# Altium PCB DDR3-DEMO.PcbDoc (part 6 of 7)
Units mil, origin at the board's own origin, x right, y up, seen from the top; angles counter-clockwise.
Board outline 2827 x 2165.35 mil, 8 copper layers (TOP, GND02, ART03, ART04, PWR05, ART06, GND07, BOTTOM); 111 components, 133 nets, 5542 pads, 873 vias.
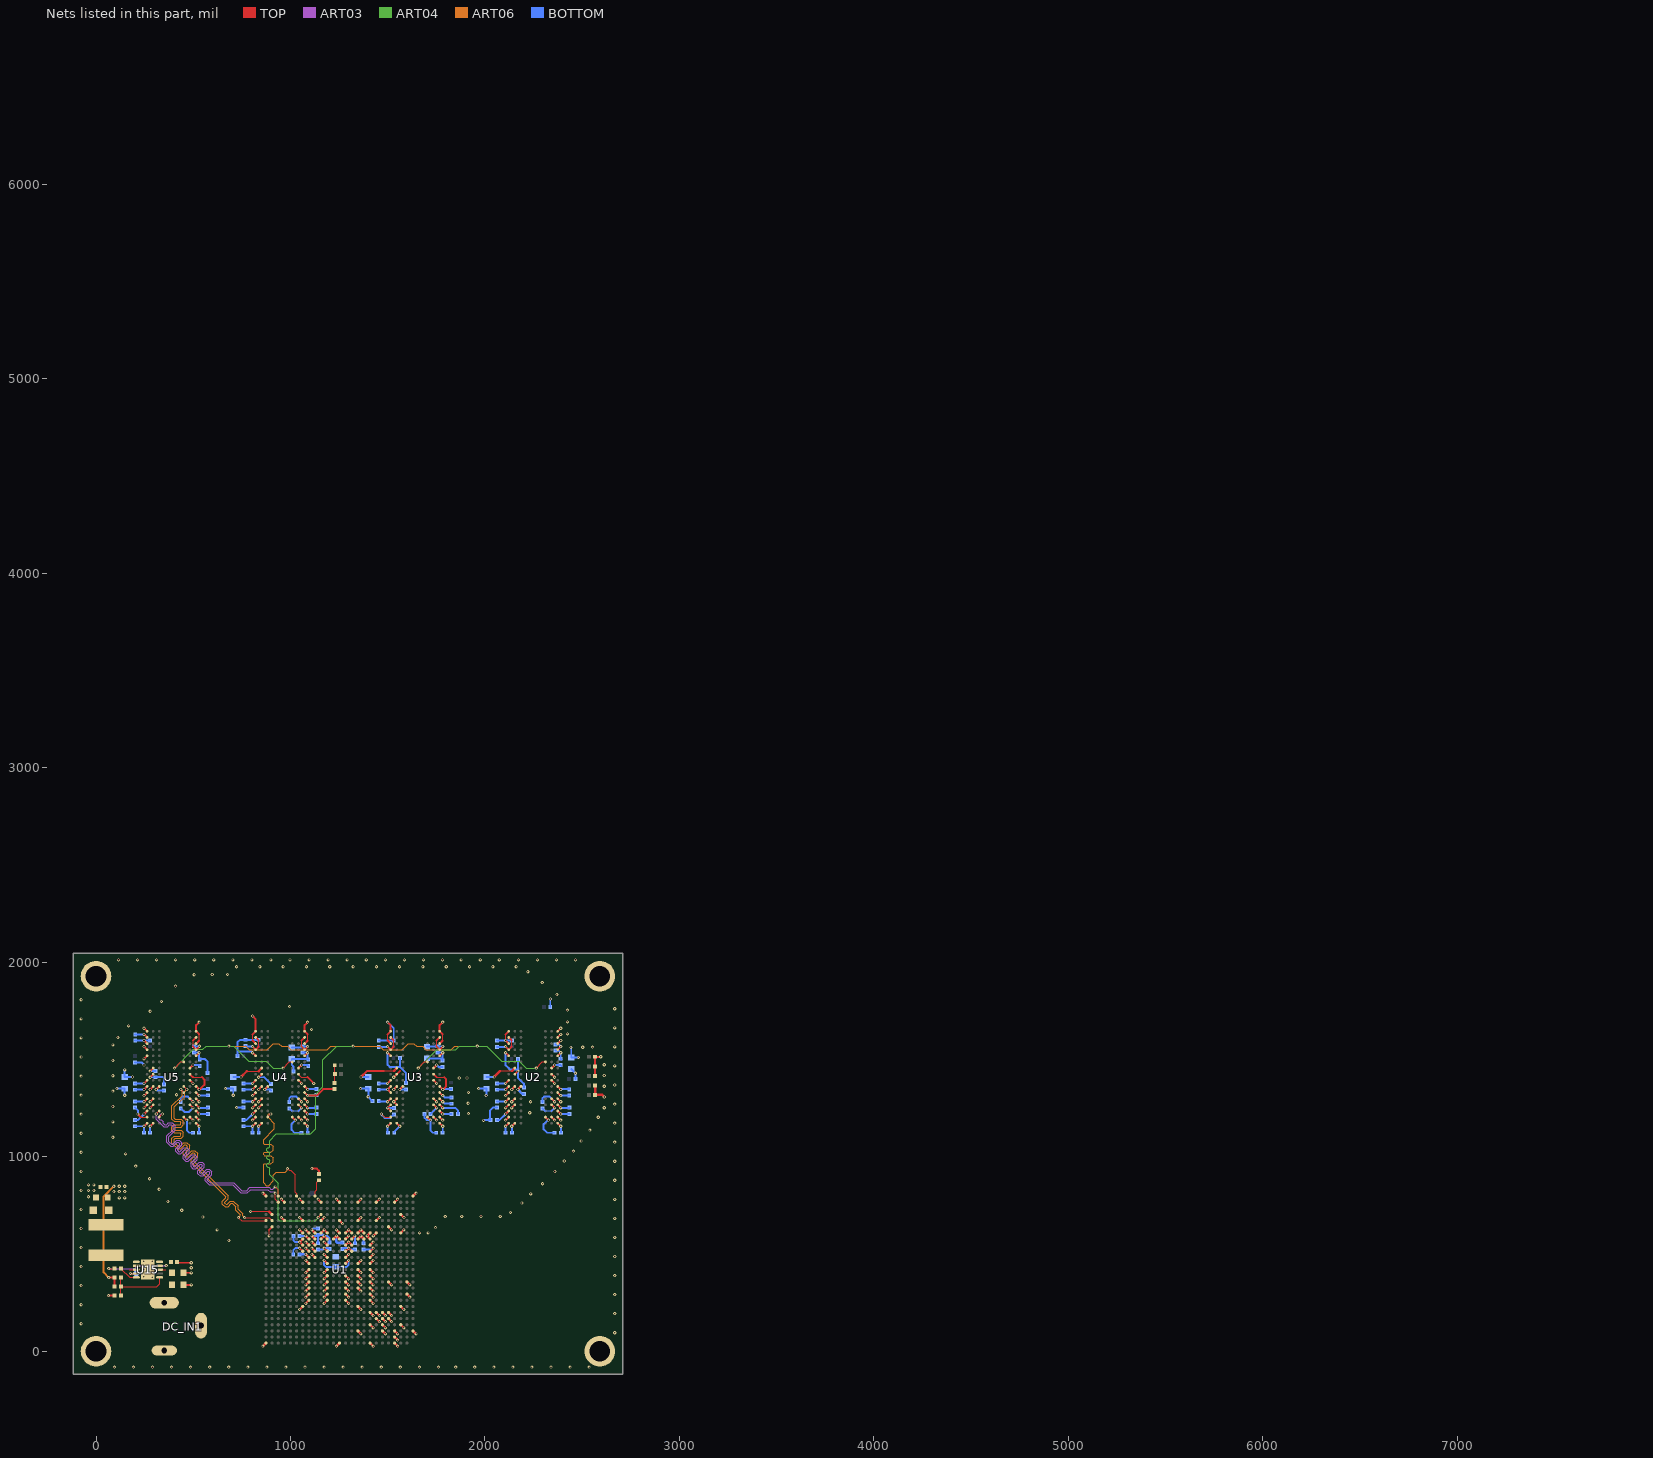
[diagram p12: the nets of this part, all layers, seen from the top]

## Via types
v1: diameter 16, hole 8, TOP to BOTTOM, tented both sides, 873 vias

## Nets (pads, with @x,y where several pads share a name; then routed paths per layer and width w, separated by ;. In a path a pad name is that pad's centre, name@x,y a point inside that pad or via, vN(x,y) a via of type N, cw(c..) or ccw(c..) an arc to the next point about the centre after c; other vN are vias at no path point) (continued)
DRAM_SDQS5_B: U1.AE20 U4.B7 | length 939.2
  TOP w4.5: U4.B7@883.39,1204.41 v1(899.13,1220.15) ; v1(984.19,939.6) 992.94,930.85 999.92,930.85 1023.42,907.35 1023.42,816.9 1031.43,808.89 U1.AE20@1031.43,797.85
  ART06 w5: v1(899.13,1220.15) 888.22,1220.15 882.42,1214.35 882.42,1205.35 917.42,1170.35 917.42,1144.38 861.42,1088.38 861.42,1067.59 865.16,1063.85 899.3,1063.85 910.07,1053.09 910.07,1033.61 899.3,1022.85 865.16,1022.85 861.42,1019.11 861.42,1009.59 865.16,1005.85 899.3,1005.85 910.07,995.09 910.07,975.61 899.3,964.85 865.16,964.85 861.42,961.11 861.42,867.35 876.42,852.35 888.45,852.35 912.42,876.32 912.42,906.35 926.42,920.35 972.42,920.35 984.19,932.12 v1(984.19,939.6)
DRAM_SDQS6: U1.AD23 U5.C7 | length 1353.9
  TOP w4.5: v1(309.66,1220.15) U5.C7@325.41,1235.9 ; v1(921.19,813.6) 921.19,782.11 U1.AD23@936.94,766.36
  ART03 w4.5: v1(309.66,1220.15) 309.66,1193.5 348.23,1154.93 367.84,1154.93 376.77,1163.85 387.07,1163.85 395.92,1155 395.92,1139.7 363.92,1107.7 363.92,1074 383.81,1054.11 397.7,1054.11 418.28,1074.69 423.48,1074.69 429.95,1068.22 429.95,1063.03 409.37,1042.45 409.37,1028.55 421.99,1015.93 435.88,1015.93 456.46,1036.51 461.66,1036.51 468.13,1030.04 468.13,1024.84 447.55,1004.26 447.55,990.37 460.17,977.75 474.07,977.75 497.2,1000.88 502.4,1000.88 508.87,994.41 508.87,989.21 485.74,966.08 485.74,952.18 498.36,939.56 512.25,939.56 535.38,962.69 540.58,962.69 547.05,956.22 547.05,951.03 523.92,927.9 523.92,914 536.54,901.38 550.44,901.38 573.57,924.51 578.76,924.51 585.23,918.04 585.23,912.84 562.1,889.71 562.1,875.82 581.63,856.29 703.63,856.29 744.57,815.35 778.42,815.35 794.92,831.85 883.92,831.85 895.42,820.35 914.44,820.35 v1(921.19,813.6)
DRAM_SDQS6_B: U1.AE23 U5.B7 | length 1356.1
  TOP w4.5: U5.B7@325.41,1204.41 v1(341.15,1220.15) ; v1(921.19,845.09) 936.94,829.34 U1.AE23@936.94,797.85
  ART03 w4.5: v1(341.15,1220.15) 334.22,1220.15 320.16,1206.09 320.16,1197.84 326.66,1191.35 334.42,1191.35 345.54,1180.23 345.54,1172.47 352.58,1165.43 363.5,1165.43 372.42,1174.35 391.42,1174.35 406.42,1159.35 406.42,1135.35 374.42,1103.35 374.42,1078.35 388.15,1064.61 393.35,1064.61 413.93,1085.19 427.83,1085.19 440.45,1072.57 440.45,1058.68 419.87,1038.1 419.87,1032.9 426.34,1026.43 431.54,1026.43 452.11,1047.01 466.01,1047.01 478.63,1034.39 478.63,1020.49 458.05,999.91 458.05,994.72 464.52,988.25 469.72,988.25 492.85,1011.38 506.74,1011.38 519.37,998.76 519.37,984.86 496.24,961.73 496.24,956.53 502.71,950.06 507.9,950.06 531.03,973.19 544.93,973.19 557.55,960.57 557.55,946.68 534.42,923.55 534.42,918.35 540.89,911.88 546.09,911.88 569.22,935.01 583.11,935.01 595.73,922.39 595.73,908.49 572.6,885.36 572.6,880.17 585.98,866.79 707.98,866.79 748.92,825.85 774.07,825.85 790.57,842.35 889.42,842.35 899.42,832.35 908.46,832.35 v1(921.19,845.09) v1@920.93,845.35
DRAM_SDQS7: U1.AA25 U5.F3 | length 1354.2
  TOP w4.5: v1(435.64,1346.14) U5.F3@451.39,1330.39 ; v1(732.22,687.62) 747.97,671.87 U1.AA25@873.95,671.87
  ART06 w5: v1(435.64,1346.14) 443.42,1338.36 443.42,1314.32 390.42,1261.32 390.42,1192.61 401.18,1181.85 432.68,1181.85 436.42,1178.11 436.42,1168.59 432.68,1164.85 401.18,1164.85 390.42,1154.09 390.42,1134.61 401.18,1123.85 432.68,1123.85 436.42,1120.11 436.42,1110.59 432.68,1106.85 401.18,1106.85 390.42,1096.09 390.42,1070.64 420.89,1040.17 436.11,1040.17 456.84,1060.9 462.12,1060.9 468.86,1054.16 468.86,1048.88 448.14,1028.15 448.13,1012.93 461.9,999.16 477.13,999.16 497.85,1019.89 503.14,1019.89 509.87,1013.15 509.87,1007.87 489.15,987.14 489.15,971.92 666.76,794.3 666.76,789.02 650.15,772.4 650.15,757.18 663.92,743.41 679.14,743.41 695.76,760.02 701.04,760.02 718.42,742.64 718.42,726.22 741.97,702.67 741.97,697.36 v1(732.22,687.62)
DRAM_SDQS7_B: U1.AA24 U5.G3 | length 1355.8
  TOP w4.5: U5.G3@451.39,1361.89 v1(467.14,1346.14) ; v1(763.71,687.62) 889.69,687.62 U1.AA24@905.44,671.87
  ART06 w5: v1(467.14,1346.14) 455.42,1334.42 455.42,1309.35 402.42,1256.35 402.42,1197.59 406.16,1193.85 437.66,1193.85 448.42,1183.09 448.42,1163.61 437.66,1152.85 406.16,1152.85 402.42,1149.11 402.42,1139.59 406.16,1135.85 437.66,1135.85 448.42,1125.09 448.42,1105.61 437.66,1094.85 406.16,1094.85 402.42,1091.11 402.42,1075.61 425.86,1052.17 431.14,1052.17 451.87,1072.9 467.09,1072.9 480.86,1059.13 480.86,1043.91 460.14,1023.18 460.13,1017.9 466.87,1011.16 472.16,1011.16 492.88,1031.89 508.11,1031.89 521.87,1018.12 521.87,1002.9 501.15,982.17 501.15,976.89 678.76,799.27 678.76,784.05 662.15,767.43 662.15,762.15 668.89,755.41 674.17,755.41 690.79,772.02 706.01,772.02 730.42,747.61 730.42,731.19 753.97,707.64 753.97,697.36 v1(763.71,687.62)
DRAM_WE_B: U1.AB16 U2.L3 U3.L3 U4.L3 U5.L3 | length 4486.2
  TOP w6: v1(404.15,1456.37) 435.65,1487.87 U5.L3@451.39,1487.87 ; v1(962.13,1456.37) 993.63,1487.87 U4.L3@1009.37,1487.87 ; v1(1141.66,687.61) U1.AB16@1157.41,703.36 ; v1(1656.65,1456.37) 1688.15,1487.87 U3.L3@1703.89,1487.87 ; v1(2263.66,1456.37) 2295.16,1487.87 U2.L3@2310.9,1487.87
  ART04 w6: v1(404.15,1456.37) 500.13,1552.35 548.89,1552.35 566.02,1569.48 v1(683.14,1569.48) 707.76,1569.48 785.89,1491.35 875.91,1491.35 910.89,1456.37 v1(962.13,1456.37) ; v1(1141.66,687.61) 1125.92,671.87 942.9,671.87 936.95,677.82 936.95,862.82 892.42,907.35 892.42,941.35 887.42,946.35 881.99,946.35 876.99,951.35 876.99,961.35 881.99,966.35 887.42,966.35 892.42,971.35 892.42,981.35 887.42,986.35 881.99,986.35 876.99,991.35 876.99,1001.35 881.99,1006.35 887.42,1006.35 892.42,1011.35 892.42,1021.35 887.42,1026.35 881.99,1026.35 876.99,1031.35 876.99,1041.35 881.99,1046.35 887.42,1046.35 892.42,1051.35 892.42,1083.35 926.42,1117.35 1103.42,1117.35 1129.42,1143.35 1129.42,1322.35 1166.42,1359.35 1166.42,1498.35 1237.55,1569.48 v1(1321.65,1569.48) ; v1(1656.65,1456.37) 1751.63,1551.35 1849.42,1551.35 1867.55,1569.48 v1(1960.15,1569.48) 2009.29,1569.48 2087.42,1491.35 2177.44,1491.35 2212.42,1456.37 v1(2263.66,1456.37)
  ART06 w4.1: v1(683.14,1569.48) 769.42,1569.48 787.55,1551.35 879.92,1551.35 910.92,1582.35 939.05,1582.35 954.05,1567.35 984.92,1567.35 1000.92,1551.35 1187.78,1551.35 1205.91,1569.48 v1(1321.65,1569.48) 1459.29,1569.48 1477.42,1551.35 1574.42,1551.35 1605.42,1582.35 1633.55,1582.35 1648.55,1567.35 1679.42,1567.35 1695.42,1551.35 1826.29,1551.35 1844.42,1569.48 v1(1960.15,1569.48)
GND: C76.2 C77.2 C78.2 C79.2 C81.2 C82.2 C83.2 C84.2 C85.2 C86.2 C87.2 C88.2 C89.2 C90.2 C91.2 C92.2 C93.2 C94.2 C95.2 C96.2 C97.2 C98.2 C99.2 C100.2 C101.2 C102.2 C103.2 C104.2 C105.2 C106.2 C107.2 C108.2 C109.2 C111.2 C112.2 C113.2 C114.2 C115.2 C116.2 C117.2 C118.2 C119.2 C120.2 C121.2 C122.2 C123.2 C124.2 C125.2 C126.2 C127.2 C128.2 C129.2 C130.2 C131.2 C132.2 C133.2 C134.2 C135.2 C136.2 C137.2 C138.2 C141.2 C142.2 C143.2 C144.2 C145.2 C146.2 C147.2 C148.2 C149.2 C150.2 C151.2 C152.2 C153.2 C154.2 C212.2 C213.2 C214.2 C216.2 C217.2 C218.2 DC_IN1.3 DC_IN1.4 M1.1 M2.1 M3.1 M4.1 R66.1 R67.1 R68.1 R70.2 R71.1 R72.1 R73.2 R135.2 U1.A4 U1.A8 U1.A13 U1.A25 U1.AA7 U1.AA10 U1.AA13 U1.AA16 U1.AA19 U1.AA22 U1.AB3 U1.AB24 U1.AD4 U1.AD7 U1.AD10 U1.AD13 U1.AD16 U1.AD19 U1.AD22 U1.AE1 U1.AE25 U1.B4 U1.C1 U1.C4 U1.C6 U1.C10 U1.D3 U1.D6 U1.D8 U1.E5 U1.E6 U1.E7 U1.F5 U1.F6 U1.F7 U1.F8 U1.G3 U1.G10 U1.G19 U1.H8 U1.H12 U1.H15 U1.H18 U1.J2 U1.J8 U1.J12 U1.J15 U1.J18 U1.K8 U1.K10 U1.K12 U1.K15 U1.K18 U1.L2 U1.L5 U1.L8 U1.L10 U1.L12 U1.L15 U1.L18 U1.M8 U1.M10 U1.M12 U1.M15 U1.M18 U1.N8 U1.N10 U1.N15 U1.N18 U1.P8 U1.P10 U1.P12 U1.P15 U1.P18 U1.R8 U1.R12 U1.R15 U1.R17 U1.T8 U1.T11 U1.T12 U1.T15 U1.T17 U1.T19 U1.U8 U1.U11 U1.U12 U1.U15 U1.U17 U1.U19 U1.V8 U1.V19 U1.W3 U1.W7 U1.W8 U1.W9 U1.W10 U1.W11 U1.W12 U1.W13 U1.W15 U1.W16 U1.W17 U1.W18 U1.W19 U1.Y5 U1.Y24 U2.A9 U2.B1 U2.B3 U2.B9 U2.D1 U2.D8 U2.E1 U2.E2 U2.E8 U2.F9 U2.G1 U2.G8 U2.G9 U2.J2 U2.J8 U2.M1 U2.M9 U2.P1 U2.P9 U2.T1 U2.T9 U3.A9 U3.B1 U3.B3 U3.B9 U3.D1 U3.D8 U3.E1 U3.E2 U3.E8 U3.F9 U3.G1 U3.G8 U3.G9 U3.J2 U3.J8 U3.M1 U3.M9 U3.P1 U3.P9 U3.T1 U3.T9 U4.A9 U4.B1 U4.B3 U4.B9 U4.D1 U4.D8 U4.E1 U4.E2 U4.E8 U4.F9 U4.G1 U4.G8 U4.G9 U4.J2 U4.J8 U4.M1 U4.M9 U4.P1 U4.P9 U4.T1 U4.T9 U5.A9 U5.B1 U5.B3 U5.B9 U5.D1 U5.D8 U5.E1 U5.E2 U5.E8 U5.F9 U5.G1 U5.G8 U5.G9 U5.J2 U5.J8 U5.M1 U5.M9 U5.P1 U5.P9 U5.T1 U5.T9 U15.G1 | length 10545.4
  TOP w6: 230.92,1204.41 U5.B9@262.42,1204.41 ; 498.42,1409.35 545.42,1409.35 ; 530.13,1598.11 530.13,1629.6 ; v1(795.2,719.11) 826.69,719.11 889.69,719.11 ; 804.65,1598.11 804.65,1629.6 ; v1(889.69,593.13) 889.69,624.62 ; U4.J2@1040.87,1424.88 1056.4,1409.35 1087.88,1409.35 ; 1088.11,1598.11 1088.11,1629.6 ; v1(1467.67,1220.15) 1483.41,1204.41 U3.B9@1514.92,1204.41 ; 1499.17,1598.11 1499.17,1629.6 ; 1750.92,1409.35 1790.42,1409.35 ; 1782.63,1598.11 1782.63,1629.6 ; v1(2106.18,1598.11) 2106.18,1629.6
  TOP w10: v1(63.42,286.35) 63.88,285.89 R135.2@95.61,285.89 ; v1(215.18,1220.15) 230.92,1204.41 ; v1(246.67,1157.16) U5.A9@262.42,1172.91 ; v1(246.67,1314.64) U5.F9@262.42,1330.39 ; v1(246.67,1346.14) U5.G9@262.42,1361.89 ; v1(246.67,1503.62) U5.M9@262.42,1519.37 ; v1(246.67,1598.11) U5.P9@262.42,1582.36 ; v1(246.67,1661.1) U5.T9@262.42,1645.35 ; v1(278.16,1251.65) U5.D8@293.91,1267.4 ; v1(278.16,1283.14) U5.E8@293.91,1298.89 ; v1(278.16,1346.14) U5.G8@293.91,1361.89 ; v1(278.16,1409.13) U5.J8@293.91,1424.88 ; C213.2@417.17,459.89 417.17,455.35 v1(489.42,455.35) ; C212.2@449.73,341.89 489.42,341.89 v1(489.42,341.35) ; C214.2@449.73,403.89 v1@489.42,403.89 ; U5.B3@451.39,1204.41 v1(467.14,1188.66) ; U5.E2@482.89,1298.89 v1(498.64,1283.14) ; U5.J2@482.89,1424.88 498.42,1409.35 ; U5.B1@514.38,1204.41 v1(530.13,1188.66) ; U5.D1@514.38,1267.4 v1(530.13,1251.65) ; U5.E1@514.38,1298.89 v1(530.13,1283.14) ; U5.G1@514.38,1361.89 v1(530.13,1346.14) 534.21,1346.14 557.42,1369.35 557.42,1397.35 545.42,1409.35 ; U5.M1@514.38,1519.37 v1(530.13,1535.12) ; U5.P1@514.38,1582.36 530.13,1598.11 ; 530.13,1629.6 U5.T1@514.38,1645.35 514.38,1676.84 v1(530.13,1692.59) ; v1(804.65,1157.16) U4.A9@820.4,1172.91 ; v1(804.65,1188.66) U4.B9@820.4,1204.41 ; v1(804.65,1314.64) U4.F9@820.4,1330.39 ; v1(804.65,1346.14) U4.G9@820.4,1361.89 ; v1(804.65,1535.12) U4.M9@820.4,1519.37 ; 804.65,1598.11 U4.P9@820.4,1582.36 ; 804.65,1629.6 U4.T9@820.4,1645.35 820.4,1708.34 v1(804.65,1724.09) ; v1(836.14,1251.65) U4.D8@851.89,1267.4 ; v1(836.14,1283.14) U4.E8@851.89,1298.89 ; v1(836.14,1346.14) U4.G8@851.89,1361.89 ; v1(836.14,1409.13) U4.J8@851.89,1424.88 ; 889.69,624.62 U1.Y24@905.44,640.37 ; U4.B3@1009.37,1204.41 v1(1025.12,1188.66) ; U4.E2@1040.87,1298.89 v1(1056.62,1283.14) ; U4.B1@1072.36,1204.41 v1(1088.11,1188.66) ; U4.D1@1072.36,1267.4 v1(1088.11,1251.65) ; U4.E1@1072.36,1298.89 v1(1088.11,1283.14) ; U4.G1@1072.36,1361.89 v1(1088.11,1346.14) ; U4.M1@1072.36,1519.37 v1(1088.11,1535.12) ; U4.P1@1072.36,1582.36 1088.11,1598.11 ; 1087.88,1409.35 v1(1119.6,1377.63) ; 1088.11,1629.6 U4.T1@1072.36,1645.35 1072.36,1676.84 v1(1088.11,1692.59) ; v1(1110.17,939.57) 1135.2,939.57 1146.42,928.35 R73.2@1146.42,911.63 ; v1(1499.17,1157.16) U3.A9@1514.92,1172.91 ; v1(1499.17,1535.12) U3.M9@1514.92,1519.37 ; 1499.17,1598.11 U3.P9@1514.92,1582.36 ; 1499.17,1629.6 U3.T9@1514.92,1645.35 1514.92,1676.84 v1(1499.17,1692.59) ; U3.F9@1514.92,1330.39 v1(1499.17,1346.14) U3.G9@1514.92,1361.89 ; v1(1530.66,1346.14) U3.G8@1546.41,1361.89 ; v1(1530.66,1409.13) U3.J8@1546.41,1424.88 1562.16,1440.63 ; U3.D8@1546.41,1267.4 v1(1530.66,1283.14) U3.E8@1546.41,1298.89 ; U3.B3@1703.89,1204.41 v1(1719.64,1188.66) ; U3.E2@1735.39,1298.89 v1(1751.14,1283.14) ; U3.J2@1735.39,1424.88 1750.92,1409.35 ; U3.B1@1766.88,1204.41 v1(1782.63,1188.66) ; U3.D1@1766.88,1267.4 v1(1782.63,1251.65) ; U3.E1@1766.88,1298.89 v1(1782.63,1283.14) ; U3.G1@1766.88,1361.89 v1(1782.63,1346.14) 1784.21,1346.14 1800.42,1362.35 1800.42,1399.35 1790.42,1409.35 ; U3.M1@1766.88,1519.37 v1(1782.63,1535.12) ; U3.P1@1766.88,1582.36 1782.63,1598.11 ; 1782.63,1629.6 U3.T1@1766.88,1645.35 1766.88,1676.84 v1(1782.63,1692.59) ; v1(2106.18,1157.16) U2.A9@2121.93,1172.91 ; v1(2106.18,1188.66) U2.B9@2121.93,1204.41 ; v1(2106.18,1314.64) U2.F9@2121.93,1330.39 ; v1(2106.18,1346.14) U2.G9@2121.93,1361.89 ; v1(2106.18,1535.12) U2.M9@2121.93,1519.37 ; v1(2106.18,1598.11) U2.P9@2121.93,1582.36 ; 2106.18,1629.6 U2.T9@2121.93,1645.35 ; v1(2137.67,1251.65) U2.D8@2153.42,1267.4 ; v1(2137.67,1283.14) U2.E8@2153.42,1298.89 ; v1(2137.67,1346.14) U2.G8@2153.42,1361.89 ; U2.J8@2153.42,1424.88 v1(2169.17,1440.63) ; U2.B3@2310.9,1204.41 v1(2326.65,1188.66) ; U2.E2@2342.4,1298.89 v1(2358.15,1283.14) ; U2.J2@2342.4,1424.88 v1(2358.15,1409.13) ; U2.B1@2373.89,1204.41 v1(2389.64,1188.66) ; U2.D1@2373.89,1267.4 v1(2389.64,1251.65) ; U2.E1@2373.89,1298.89 v1(2389.64,1283.14) ; U2.G1@2373.89,1361.89 v1(2389.64,1346.14) ; U2.M1@2373.89,1519.37 v1(2389.64,1535.12) ; U2.P1@2373.89,1582.36 v1(2389.64,1598.11) ; U2.T1@2373.89,1645.35 v1(2389.64,1661.1) ; R70.2@2566.7,1416.35 C81.2@2566.7,1465.35 C82.2@2566.7,1514.35 v1(2595.42,1514.35)
  TOP w12: v1(858.2,26.2) U1.A25@873.95,41.95 ; v1(858.2,813.6) U1.AE25@873.95,797.85 ; 889.69,719.11 U1.AB24@905.44,703.36 ; v1(952.69,687.62) U1.AA22@968.44,671.87 ; v1(952.69,782.11) U1.AD22@968.44,766.36 ; v1(1047.17,215.17) U1.G19@1062.92,230.92 ; v1(1047.17,530.14) U1.T19@1062.92,514.39 ; v1(1047.17,624.63) U1.W19@1062.92,608.88 ; v1(1047.17,687.62) U1.AA19@1062.92,671.87 ; v1(1047.17,782.11) U1.AD19@1062.92,766.36 ; U1.U19@1062.92,545.88 v1(1047.17,561.63) U1.V19@1062.92,577.38 ; v1(1078.67,246.67) U1.H18@1094.42,262.42 ; v1(1078.67,278.17) U1.J18@1094.42,293.92 ; v1(1078.67,309.66) U1.K18@1094.42,325.41 ; v1(1078.67,341.16) U1.L18@1094.42,356.91 ; v1(1078.67,372.65) U1.M18@1094.42,388.4 ; v1(1078.67,404.15) U1.N18@1094.42,419.9 ; v1(1078.67,467.15) U1.P18@1094.42,451.4 ; v1(1078.67,624.63) U1.W18@1094.42,608.88 ; v1(1110.17,498.64) U1.R17@1125.92,482.89 ; v1(1110.17,530.14) U1.T17@1125.92,514.39 ; v1(1110.17,561.63) U1.U17@1125.92,545.88 ; v1(1110.17,624.63) U1.W17@1125.92,608.88 ; v1(1141.66,782.11) U1.AD16@1157.41,766.36 ; U1.W16@1157.41,608.88 v1(1173.16,624.63) U1.W15@1188.91,608.88 ; U1.AA16@1157.41,671.87 v1(1173.16,687.62) ; v1(1173.16,246.67) U1.H15@1188.91,262.42 ; v1(1173.16,278.17) U1.J15@1188.91,293.92 ; v1(1173.16,309.66) U1.K15@1188.91,325.41 ; v1(1173.16,341.16) U1.L15@1188.91,356.91 ; v1(1173.16,372.65) U1.M15@1188.91,388.4 ; v1(1173.16,404.15) U1.N15@1188.91,419.9 ; v1(1173.16,467.15) U1.P15@1188.91,451.4 ; v1(1173.16,498.64) U1.R15@1188.91,482.89 ; v1(1173.16,530.14) U1.T15@1188.91,514.39 ; v1(1173.16,561.63) U1.U15@1188.91,545.88 ; v1(1236.15,26.2) U1.A13@1251.9,41.95 ; v1(1236.15,624.63) U1.W13@1251.9,608.88 ; v1(1236.15,782.11) U1.AD13@1251.9,766.36 ; U1.AA13@1251.9,671.87 v1(1267.65,656.12) ; U1.H12@1283.4,262.42 v1(1299.15,246.67) ; U1.J12@1283.4,293.92 v1(1299.15,278.17) ; U1.K12@1283.4,325.41 v1(1299.15,309.66) ; U1.L12@1283.4,356.91 v1(1299.15,341.16) ; U1.M12@1283.4,388.4 v1(1299.15,372.65) ; U1.P12@1283.4,451.4 v1(1299.15,467.15) ; U1.R12@1283.4,482.89 v1(1299.15,498.64) ; U1.T12@1283.4,514.39 v1(1299.15,530.14) U1.T11@1314.89,514.39 ; U1.U12@1283.4,545.88 v1(1299.15,561.63) U1.U11@1314.89,545.88 ; U1.W12@1283.4,608.88 v1(1299.15,624.63) U1.W11@1314.89,608.88 ; U1.C10@1346.39,104.94 v1(1362.14,89.19) ; U1.G10@1346.39,230.92 v1(1362.14,215.17) ; U1.K10@1346.39,325.41 v1(1362.14,309.66) ; U1.L10@1346.39,356.91 v1(1362.14,341.16) ; U1.M10@1346.39,388.4 v1(1362.14,372.65) ; U1.N10@1346.39,419.9 v1(1362.14,404.15) ; U1.P10@1346.39,451.4 v1(1362.14,467.15) ; U1.W10@1346.39,608.88 v1(1362.14,624.63) U1.W9@1377.88,608.88 ; U1.AA10@1346.39,671.87 v1(1362.14,687.62) ; U1.AD10@1346.39,766.36 v1(1362.14,782.11) ; U1.A8@1409.38,41.95 v1(1425.13,26.2) ; U1.D8@1409.38,136.44 v1(1425.13,120.69) ; U1.F8@1409.38,199.43 v1(1425.13,183.68) ; U1.H8@1409.38,262.42 v1(1425.13,246.67) ; U1.J8@1409.38,293.92 v1(1425.13,278.17) ; U1.K8@1409.38,325.41 v1(1425.13,309.66) ; U1.L8@1409.38,356.91 v1(1425.13,341.16) ; U1.M8@1409.38,388.4 v1(1425.13,372.65) ; U1.N8@1409.38,419.9 v1(1425.13,404.15) ; U1.P8@1409.38,451.4 v1(1425.13,467.15) ; U1.R8@1409.38,482.89 v1(1425.13,498.64) ; U1.T8@1409.38,514.39 v1(1425.13,530.14) ; U1.U8@1409.38,545.88 v1(1425.13,561.63) ; U1.V8@1409.38,577.38 v1(1393.63,593.13) U1.W8@1409.38,608.88 ; v1(1425.13,593.13) U1.W7@1440.88,608.88 ; U1.E7@1440.88,167.93 v1(1456.63,152.18) ; U1.F7@1440.88,199.43 v1(1456.63,183.68) ; U1.AA7@1440.88,671.87 v1(1456.63,687.62) ; U1.AD7@1440.88,766.36 v1(1456.63,782.11) ; U1.C6@1472.37,104.94 v1(1488.12,89.19) ; U1.D6@1472.37,136.44 v1(1488.12,120.69) ; U1.E6@1472.37,167.93 v1(1488.12,152.18) ; U1.F6@1472.37,199.43 v1(1488.12,183.68) ; U1.E5@1503.87,167.93 v1(1519.62,152.18) ; U1.F5@1503.87,199.43 v1(1519.62,183.68) ; U1.L5@1503.87,356.91 v1(1519.62,341.16) ; U1.Y5@1503.87,640.37 v1(1519.62,624.62) ; U1.A4@1535.36,41.95 v1(1551.11,26.2) ; U1.B4@1535.36,73.44 v1(1551.11,57.69) ; U1.C4@1535.36,104.94 v1(1551.11,89.19) ; U1.AD4@1535.36,766.36 v1(1551.11,782.11) ; U1.D3@1566.86,136.44 v1(1582.61,120.69) ; U1.G3@1566.86,230.92 v1(1582.61,215.17) ; U1.W3@1566.86,608.88 v1(1582.61,624.63) ; U1.AB3@1566.86,703.36 v1@1582.61,687.61 ; U1.J2@1598.36,293.92 v1(1614.11,278.17) ; U1.L2@1598.36,356.91 v1(1614.11,341.16) ; U1.C1@1629.85,104.94 v1(1645.6,89.19) ; U1.AE1@1629.85,797.85 v1(1645.6,813.6)
  BOTTOM w10: v1(107.42,1350.35) 107.5,1350.43 C87.2@147.42,1350.43 v1(147.42,1316.35) v1@146.42,1315.35 ; C88.2@201.28,1157.07 201.38,1157.16 v1(246.67,1157.16) 246.14,1156.63 C113.2@246.14,1123.59 ; C93.2@201.28,1253.07 215.18,1239.16 v1(215.18,1220.15) ; C112.2@201.28,1345.07 245.6,1345.07 v1(246.67,1346.14) ; R72.1@201.28,1485.07 233.72,1485.07 v1(246.67,1472.12) ; C92.2@201.42,1597.07 245.63,1597.07 v1(246.67,1598.11) 277.89,1598.11 C83.2@278.42,1598.63 ; v1(278.16,1409.13) C91.2@305.42,1409.07 ; C115.2@348.42,1372.63 348.42,1405.35 344.42,1409.35 C91.2@305.7,1409.35 ; C116.2@435.42,1281.63 435.42,1300.35 444.42,1309.35 472.43,1309.35 v1(498.64,1283.14) ; v1(467.14,1188.66) 467.14,1135.63 479.18,1123.59 C114.2@498.14,1123.59 ; C111.2@503.42,1536.07 529.18,1536.07 v1(530.13,1535.12) C117.2@530.13,1502.93 ; v1(530.13,1251.65) 574.44,1251.65 C89.2@575.42,1252.63 ; v1(530.13,1346.14) 532.62,1348.63 C90.2@575.52,1348.63 ; C117.2@533.42,1499.63 C117.2@530.13,1502.93 ; C84.2@573.42,1431.63 573.42,1488.35 558.84,1502.93 C117.2@530.13,1502.93 ; v1(665.4,1350.35) 665.48,1350.43 C125.2@705.4,1350.43 v1(705.4,1316.35) v1@704.4,1315.35 ; v1(722.42,1253.35) 722.7,1253.07 C131.2@759.26,1253.07 ; R71.1@726.98,1517.35 726.98,1541.35 ; C146.2@759.26,1157.07 759.36,1157.16 v1(804.65,1157.16) 804.12,1156.63 C142.2@804.14,1123.59 ; C145.2@759.26,1345.07 803.58,1345.07 v1(804.65,1346.14) ; v1(804.65,1535.12) 798.42,1541.35 726.98,1541.35 ; v1(836.14,1409.13) 863.33,1409.13 863.4,1409.07 863.68,1409.35 864.42,1409.35 895.14,1378.63 C129.2@898.4,1378.63 ; C86.2@836.4,1598.63 835.87,1598.11 832.21,1601.77 C130.2@769.42,1601.77 740.84,1601.77 726.98,1587.91 726.98,1541.35 ; C147.2@993.4,1281.63 993.4,1300.35 1002.4,1309.35 1030.41,1309.35 v1(1056.62,1283.14) ; C106.2@1014.14,498.35 1014.14,519.07 1025.21,530.14 v1(1047.17,530.14) ; C85.2@1014.42,1437.63 1014.42,1464.35 1006.42,1472.35 C141.2@1006.42,1502.51 1087.69,1502.51 C127.2@1088.11,1502.93 ; C104.2@1014.89,593.13 1014.89,569.88 1022.42,562.35 1046.45,562.35 v1(1047.17,561.63) ; v1(1025.12,1188.66) 1005.42,1168.96 1005.42,1138.35 1020.18,1123.59 C143.2@1056.12,1123.59 ; C126.2@1061.4,1536.07 1087.16,1536.07 v1(1088.11,1535.12) C127.2@1088.11,1502.93 ; v1(1088.11,1251.65) 1132.42,1251.65 C128.2@1133.4,1252.63 ; v1(1088.11,1346.14) 1090.6,1348.63 C144.2@1133.5,1348.63 ; C127.2@1091.4,1499.63 C127.2@1088.11,1502.93 ; v1(1110.17,624.63) 1117.18,631.63 C102.2@1140.42,631.63 ; C103.2@1141.42,523.07 1166.09,523.07 v1(1173.16,530.14) 1196.35,530.14 C109.2@1200.42,526.07 ; v1(1173.16,467.15) 1173.16,442.61 1181.6,434.17 C101.2@1233.42,434.17 1289.24,434.17 1299.15,444.08 v1(1299.15,467.15) ; C107.2@1266.42,526.07 1270.49,530.14 v1(1299.15,530.14) 1306.22,523.07 C105.2@1331.42,523.07 ; v1(1359.92,1350.35) 1360,1350.43 C118.2@1399.92,1350.43 1399.92,1316.35 1398.92,1315.35 v1(1398.92,1308.93) C95.2@1421.5,1286.35 ; C108.2@1375.42,523.21 1418.2,523.21 v1(1425.13,530.14) ; C100.2@1453.78,1345.07 1498.1,1345.07 v1(1499.17,1346.14) ; C122.2@1453.92,1597.07 1498.13,1597.07 1499.17,1598.11 1530.39,1598.11 C78.2@1530.92,1598.63 1530.92,1660.84 v1(1499.17,1692.59) ; v1(1467.67,1220.15) 1467.67,1216.1 1483.42,1200.35 1513.7,1200.35 C96.2@1531.42,1218.07 ; C97.2@1498.64,1123.59 1498.64,1156.63 v1(1499.17,1157.16) ; v1@1501.42,1532.87 v1(1499.17,1535.12) 1499.17,1472.6 1509.7,1462.07 1562.7,1462.07 ; R67.1@1562.7,1507.35 1562.7,1462.07 ; C99.2@1592.92,1378.63 1592.92,1431.85 1562.7,1462.07 ; C120.2@1688.14,1220.35 1688.14,1200.63 1699.42,1189.35 1718.95,1189.35 v1(1719.64,1188.66) 1719.64,1135.63 1731.68,1123.59 C119.2@1749.14,1123.59 C119.2@1750.64,1123.59 ; C94.2@1701.42,1506.51 1779.04,1506.51 ; C123.2@1755.92,1536.07 1781.68,1536.07 1781.15,1535.54 C124.2@1781.15,1494.4 ; v1(1782.63,1251.65) 1847.12,1251.65 1860.2,1238.57 C121.2@1860.2,1220.35 ; v1(1782.63,1283.14) 1792.7,1273.07 C98.2@1828.02,1273.07 ; v1(1782.63,1346.14) 1785.12,1348.63 C79.2@1824.42,1348.63 C79.2@1828.02,1348.63 ; v1(1966.93,1350.35) 1967.01,1350.43 C148.2@2006.93,1350.43 2006.93,1316.35 v1(2005.93,1315.35) ; v1(1992.42,1187.35) 1994.42,1189.35 C154.2@2028.51,1189.35 2026.42,1191.44 2026.42,1239.35 2040.14,1253.07 C153.2@2060.79,1253.07 ; C149.2@2060.79,1345.07 2105.11,1345.07 v1(2106.18,1346.14) ; C137.2@2060.93,1597.07 2105.14,1597.07 v1(2106.18,1598.11) 2137.4,1598.11 C76.2@2137.93,1598.63 ; C135.2@2105.65,1123.59 2105.65,1156.63 v1(2106.18,1157.16) ; v1(2106.18,1535.12) 2106.18,1469.59 2126.7,1449.07 2169.7,1449.07 ; v1(2169.17,1440.63) 2169.17,1407.6 2200.42,1376.35 C134.2@2200.42,1355.63 ; R66.1@2169.7,1502.35 2169.7,1449.07 ; v1@2173.65,1445.11 2169.7,1449.07 ; C133.2@2294.93,1281.63 2294.93,1300.35 2303.93,1309.35 2331.94,1309.35 v1(2358.15,1283.14) 2358.36,1283.35 v1@2360.42,1283.35 ; v1(2326.65,1188.66) 2321.73,1188.66 2301.42,1168.35 2301.42,1141.35 2319.18,1123.59 C136.2@2357.65,1123.59 ; R68.1@2335.7,1771.35 2335.7,1810.63 v1(2336.42,1811.35) ; C138.2@2362.93,1546.07 2378.69,1546.07 v1(2389.64,1535.12) 2389.64,1502.93 C151.2@2392.93,1499.63 ; v1(2389.64,1251.65) 2433.95,1251.65 C152.2@2434.93,1252.63 ; v1(2389.64,1346.14) 2392.13,1348.63 C150.2@2435.03,1348.63 ; C132.2@2443.42,1451.51 v1(2465.21,1429.72) C77.2@2465.21,1399.35 ; C91.2@305.42,1409.07 305.57,1409.35 C91.2@305.7,1409.35 ; C91.2@305.42,1409.07 C91.2@305.42,1409.07 C91.2@305.7,1409.35
  other v1: 94.42,-81.65 192.42,-81.65 290.42,-81.65 388.42,-81.65 486.42,-81.65 584.42,-81.65 682.42,-81.65 780.42,-81.65 878.42,-81.65 976.42,-81.65 1074.42,-81.65 1172.42,-81.65 1270.42,-81.65 1368.42,-81.65 1466.42,-81.65 1564.42,-81.65 1662.42,-81.65 1760.42,-81.65 1849.42,-81.65 1947.42,-81.65 2045.42,-81.65 2143.42,-81.65 2241.42,-81.65 2339.42,-81.65 2437.42,-81.65 2535.42,-81.65 2667.42,95.35 -76.58,141.35 2667.42,193.35 -76.58,239.35 2667.42,291.35 -76.58,337.35 289.42,380.35 246.42,382.35 2667.42,389.35 489.42,403.35 289.42,421.35 246.42,422.35 489.42,429.35 -76.58,435.35 246.42,462.35 289.42,462.35 2667.42,487.35 -76.58,533.35 683.42,570.35 2667.42,585.35 1663.42,608.88 1707.42,608.88 622.42,624.35 -76.58,631.35 1745.42,636.35 2667.42,683.35 1583.42,687.62 549.42,690.35 1795.42,692.35 1880.42,693.35 1979.42,693.35 2078.42,693.35 2130.42,714.35 440.42,725.35 -76.58,729.35 2189.42,762.35 369.42,770.35 2667.42,781.35 -39.11,794.35 2235.42,809.35 -76.58,827.35 -39.11,827.35 -11.11,827.35 324.42,833.35 -39.11,855.35 -11.11,855.35 2296.42,861.35 2667.42,879.35 275.42,887.35 2359.42,924.35 -76.58,925.35 204.42,952.35 2667.42,977.35 2407.42,978.35 152.42,1015.35 -76.58,1023.35 2454.42,1029.35 2667.42,1075.35 2494.42,1081.35 86.42,1100.35 -76.58,1121.35 2539.42,1137.35 2667.42,1173.35 86.42,1179.52 2582.42,1203.35 -76.58,1219.35 1914.42,1222.35 2230.42,1226.35 2613.42,1252.35 86.42,1258.68 2667.42,1271.35 1913.42,1275.35 2234.42,1283.35 -76.58,1317.35 414.41,1319.35 1914.42,1331.35 86.42,1337.85 2613.42,1362.85 2667.42,1369.35 1867.42,1405.35 1907.42,1405.35 -76.58,1415.35 86.42,1417.02 2613.42,1418.1 2667.42,1467.35 2613.42,1473.35 86.42,1496.18 -76.58,1513.35 2502.42,1563.35 2553.42,1564.35 2667.42,1565.35 86.42,1575.35 -76.58,1611.35 112.42,1614.35 2423.42,1632.35 1108.42,1655.35 2667.42,1663.35 167.42,1673.35 2423.42,1693.35 -76.58,1709.35 278.42,1748.35 2423.42,1754.35 2667.42,1761.35 995.42,1772.35 336.42,1799.35 -76.58,1807.35 2369.42,1834.35 408.42,1877.35 2294.42,1895.35 504.42,1936.35 597.42,1937.35 676.42,1938.35 2220.42,1951.35 722.42,1977.35 842.25,1977.35 962.09,1977.35 1081.92,1977.35 1201.75,1977.35 1321.59,1977.35 1441.42,1977.35 1561.25,1977.35 1681.09,1977.35 1800.92,1977.35 1920.75,1977.35 2040.59,1977.35 2160.42,1977.35 115.42,2012.35 213.42,2012.35 311.42,2012.35 409.42,2012.35 507.42,2012.35 605.42,2012.35 703.42,2012.35 801.42,2012.35 899.42,2012.35 997.42,2012.35 1095.42,2012.35 1193.42,2012.35 1291.42,2012.35 1389.42,2012.35 1487.42,2012.35 1585.42,2012.35 1683.42,2012.35 1781.42,2012.35 1877.42,2012.35 1975.42,2012.35 2073.42,2012.35 2171.42,2012.35 2269.42,2012.35 2367.42,2012.35 2465.42,2012.35
N29831394: C140.2 R76.2 R78.1 | length 90.6
  TOP w6: C140.2@1226.69,1380.35 1227.42,1381.08 R78.1@1227.42,1470.63
N31313342: C212.1 C213.1 C214.1 DC_IN1.5 R132.1 U15.8 U15.9 U15.10 | length 362.6
  TOP w6: v1(65.42,425.35) 65.88,424.89 R132.1@95.61,424.89 ; U15.8@326.89,419.89 357.39,419.89
  ART03 w6: v1(65.42,425.35) 199.42,425.35 214.42,440.35 v1(360.89,440.35)
N31313358: L6.1 U15.1 U15.2 U15.3 | length 35.9
  TOP w6: 170.96,419.89 U15.3@206.89,419.89
N31313368: C215.2 R133.2 R135.1 U15.6 | length 330.8
  TOP w6: R135.1@127.89,285.89 C215.2@127.89,332.22 ; R133.2@127.89,378.56 C215.2@127.89,332.22 ; U15.6@326.89,379.88 326.89,346.82 312.29,332.22 C215.2@127.89,332.22
N31313399: TP11.1 U15.4 | length 61.3
  TOP w6: v1(176.42,400.35) 176.89,399.88 U15.4@206.89,399.88
  BOTTOM w6: v1(176.42,400.35) 176.88,399.89 TP11.1@206.89,399.89
N31313405: R132.2 U15.5 | length 97.6
  TOP w6: R132.2@127.89,424.89 172.9,379.88 U15.5@206.89,379.88
VDD_1V5: C80.1 C87.1 C88.1 C89.1 C90.1 C91.1 C92.1 C93.1 C94.1 C95.1 C96.1 C97.1 C98.1 C99.1 C100.1 C101.1 C102.1 C103.1 C104.1 C105.1 C106.1 C107.1 C108.1 C109.1 C111.1 C112.1 C113.1 C114.1 C115.1 C116.1 C117.1 C118.1 C119.1 C120.1 C121.1 C122.1 C123.1 C124.1 C125.1 C126.1 C127.1 C128.1 C129.1 C130.1 C131.1 C132.1 C133.1 C134.1 C135.1 C136.1 C137.1 C138.1 C140.1 C141.1 C142.1 C143.1 C144.1 C145.1 C146.1 C147.1 C148.1 C149.1 C150.1 C151.1 C152.1 C153.1 C154.1 C215.1 C216.1 C217.1 C218.1 L6.2 R69.1 R133.1 U1.R18 U1.T18 U1.U18 U1.V9 U1.V10 U1.V11 U1.V12 U1.V13 U1.V14 U1.V15 U1.V16 U1.V17 U1.V18 U2.A1 U2.A8 U2.B2 U2.C1 U2.C9 U2.D2 U2.D9 U2.E9 U2.F1 U2.G7 U2.H2 U2.H9 U2.K2 U2.K8 U2.N1 U2.N9 U2.R1 U2.R9 U3.A1 U3.A8 U3.B2 U3.C1 U3.C9 U3.D2 U3.D9 U3.E9 U3.F1 U3.G7 U3.H2 U3.H9 U3.K2 U3.K8 U3.N1 U3.N9 U3.R1 U3.R9 U4.A1 U4.A8 U4.B2 U4.C1 U4.C9 U4.D2 U4.D9 U4.E9 U4.F1 U4.G7 U4.H2 U4.H9 U4.K2 U4.K8 U4.N1 U4.N9 U4.R1 U4.R9 U5.A1 U5.A8 U5.B2 U5.C1 U5.C9 U5.D2 U5.D9 U5.E9 U5.F1 U5.G7 U5.H2 U5.H9 U5.K2 U5.K8 U5.N1 U5.N9 U5.R1 U5.R9 | length 6335.8
  TOP w6: v1(65.42,379.02) v1@65.88,378.56 ; 498.88,1566.36 498.88,1598.35 ; 775.4,1440.35 835.87,1440.35 ; 835.9,1566.36 835.9,1598.35 ; 1056.86,1566.36 1056.86,1598.35 ; 1481.42,1441.35 1531.39,1441.35 ; 1530.42,1566.36 1530.42,1598.35 ; 1751.38,1566.36 1751.38,1598.35 ; 2077.93,1441.35 2138.4,1441.35 ; 2137.43,1566.36 2137.43,1598.35
  TOP w10: v1@65.88,378.56 R133.1@95.61,378.56 C215.1@95.61,332.22 ; v1(246.67,1220.15) U5.C9@262.42,1235.9 ; v1(246.67,1251.65) U5.D9@262.42,1267.4 ; v1(246.67,1283.14) U5.E9@262.42,1298.89 ; v1(246.67,1377.63) U5.H9@262.42,1393.38 ; v1(246.67,1566.61) U5.N9@262.42,1550.86 ; v1(246.67,1629.6) U5.R9@262.42,1613.85 ; v1(278.16,1157.16) U5.A8@293.91,1172.91 ; v1(278.16,1440.62) U5.K8@293.91,1456.37 ; v1(309.66,1346.14) U5.G7@325.41,1361.89 ; U5.B2@482.89,1204.41 v1(498.64,1188.66) ; U5.D2@482.89,1267.4 v1(498.64,1251.65) ; U5.H2@482.89,1393.38 v1(498.64,1377.63) ; U5.K2@482.89,1456.37 v1(498.64,1472.12) ; 498.88,1566.36 U5.N1@514.38,1550.86 v1@530.13,1566.61 ; 498.88,1598.35 U5.R1@514.38,1613.85 ; U5.A1@514.38,1172.91 v1(530.13,1157.16) ; U5.C1@514.38,1235.9 v1(530.13,1220.15) ; U5.F1@514.38,1330.39 v1(530.13,1314.64) ; v1(804.65,1220.15) U4.C9@820.4,1235.9 ; v1(804.65,1251.65) U4.D9@820.4,1267.4 ; v1(804.65,1283.14) U4.E9@820.4,1298.89 ; v1(804.65,1377.63) U4.H9@820.4,1393.38 ; v1(804.65,1566.61) U4.N9@820.4,1550.86 835.9,1566.36 ; U4.R9@820.4,1613.85 835.9,1598.35 ; v1(836.14,1157.16) U4.A8@851.89,1172.91 ; v1(867.64,1346.14) U4.G7@883.39,1361.89 ; U4.B2@1040.87,1204.41 v1(1056.62,1188.66) ; U4.D2@1040.87,1267.4 v1(1056.62,1251.65) ; U4.H2@1040.87,1393.38 v1(1056.62,1377.63) ; U4.K2@1040.87,1456.37 v1(1056.62,1472.12) ; 1056.86,1566.36 U4.N1@1072.36,1550.86 v1(1088.11,1566.61) ; 1056.86,1598.35 U4.R1@1072.36,1613.85 ; U4.A1@1072.36,1172.91 v1(1088.11,1157.16) ; U4.C1@1072.36,1235.9 v1(1088.11,1220.15) ; U4.F1@1072.36,1330.39 v1(1088.11,1314.64) 1134.71,1314.64 1168.14,1348.07 C140.1@1226.69,1348.07 ; v1(1362.42,1410.35) 1393.42,1441.35 1481.42,1441.35 ; v1(1499.17,1283.14) U3.E9@1514.92,1298.89 ; v1(1499.17,1377.63) U3.H9@1514.92,1393.38 ; v1(1499.17,1566.61) U3.N9@1514.92,1550.86 1530.42,1566.36 ; U3.C9@1514.92,1235.9 1499.17,1251.65 U3.D9@1514.92,1267.4 ; U3.R9@1514.92,1613.85 1530.42,1598.35 ; U3.A8@1546.41,1172.91 v1(1562.16,1157.16) ; v1(1562.16,1346.14) U3.G7@1577.91,1361.89 ; U3.B2@1735.39,1204.41 v1(1751.14,1188.66) ; U3.D2@1735.39,1267.4 v1(1751.14,1251.65) ; U3.H2@1735.39,1393.38 v1(1751.14,1377.63) ; U3.K2@1735.39,1456.37 v1(1751.14,1472.12) ; 1751.38,1566.36 U3.N1@1766.88,1550.86 ; 1751.38,1598.35 U3.R1@1766.88,1613.85 ; U3.A1@1766.88,1172.91 v1(1782.63,1157.16) ; U3.C1@1766.88,1235.9 v1(1782.63,1220.15) ; U3.F1@1766.88,1330.39 v1(1782.63,1314.64) ; v1(2106.18,1220.15) U2.C9@2121.93,1235.9 ; v1(2106.18,1251.65) U2.D9@2121.93,1267.4 ; v1(2106.18,1283.14) U2.E9@2121.93,1298.89 ; v1(2106.18,1377.63) U2.H9@2121.93,1393.38 ; v1(2106.18,1566.61) U2.N9@2121.93,1550.86 2137.43,1566.36 ; U2.R9@2121.93,1613.85 2137.43,1598.35 ; v1(2137.67,1157.16) U2.A8@2153.42,1172.91 ; v1(2169.17,1346.14) U2.G7@2184.92,1361.89 ; U2.B2@2342.4,1204.41 v1(2358.15,1188.66) ; U2.D2@2342.4,1267.4 v1(2358.15,1251.65) ; U2.H2@2342.4,1393.38 v1(2358.15,1377.63) ; U2.K2@2342.4,1456.37 v1(2358.15,1472.12) ; U2.A1@2373.89,1172.91 v1(2389.64,1157.16) ; U2.C1@2373.89,1235.9 v1(2389.64,1220.15) ; U2.F1@2373.89,1330.39 v1(2389.64,1314.64) ; U2.N1@2373.89,1550.86 v1(2389.64,1566.61) ; U2.R1@2373.89,1613.85 v1(2389.64,1629.6) ; U3.N1@1766.88,1550.86 1782.63,1566.61 U3.N1@1766.88,1550.86
  TOP w12: v1(745.4,1410.35) 775.4,1440.35 ; 835.87,1440.35 U4.K8@851.89,1456.37 ; v1(1078.67,498.64) U1.R18@1094.42,482.89 ; v1(1078.67,530.14) U1.T18@1094.42,514.39 ; v1(1078.67,561.63) U1.U18@1094.42,545.88 ; v1(1078.67,593.13) U1.V18@1094.42,577.38 ; v1(1110.17,593.13) U1.V17@1125.92,577.38 ; U1.V16@1157.41,577.38 v1(1173.16,593.13) U1.V15@1188.91,577.38 ; U1.V14@1220.4,577.38 v1(1236.15,593.13) U1.V13@1251.9,577.38 ; U1.V12@1283.4,577.38 v1(1299.15,593.13) ; U1.V11@1314.89,577.38 v1(1330.64,593.13) ; U1.V10@1346.39,577.38 v1(1362.14,593.13) U1.V9@1377.88,577.38 ; 1531.39,1441.35 U3.K8@1546.41,1456.37 ; v1(2046.85,1410.27) 2077.93,1441.35 ; 2138.4,1441.35 U2.K8@2153.42,1456.37 ; C80.1@2566.7,1367.35 R69.1@2566.7,1318.35 2602.67,1318.35 v1(2613.42,1307.6)
  ART06 w10: v1(65.42,379.02) 38.42,406.02 38.42,795.89 v1(91.42,848.89)
  BOTTOM w5: 1006.4,1236.35 1041.32,1236.35 ; 2308.38,1235.9 2342.4,1235.9
  BOTTOM w10: v1(147.42,1447.35) C87.1@147.42,1410.27 187.34,1410.27 v1(187.42,1410.35) ; C88.1@201.28,1189.35 215.87,1189.35 v1(246.67,1220.15) ; C93.1@201.28,1285.35 244.46,1285.35 v1(246.67,1283.14) ; C112.1@201.28,1377.35 246.39,1377.35 v1(246.67,1377.63) ; C92.1@201.42,1629.35 246.42,1629.35 v1(246.67,1629.6) ; v1(278.16,1157.16) 278.42,1156.9 C113.1@278.42,1123.59 ; v1(278.16,1440.62) 304.69,1440.62 C91.1@305.42,1441.35 ; v1(309.66,1346.14) 309.87,1346.35 315.87,1340.35 C115.1@348.42,1340.35 ; C116.1@435.42,1249.35 453.42,1231.35 478.34,1231.35 v1(498.64,1251.65) ; v1(498.64,1472.12) 528.65,1472.12 C117.1@533.42,1467.35 ; C111.1@503.42,1568.35 530.87,1568.35 v1(531.13,1568.61) ; v1(530.13,1157.16) 530.42,1156.87 C114.1@530.42,1123.59 ; v1(530.13,1220.15) 530.33,1220.35 C89.1@575.42,1220.35 ; v1(530.13,1314.64) 573.81,1314.64 C90.1@575.52,1316.35 ; C125.1@705.4,1410.27 745.32,1410.27 v1(745.4,1410.35) ; C146.1@759.26,1189.35 773.85,1189.35 v1(804.65,1220.15) ; C131.1@759.26,1285.35 802.44,1285.35 v1(804.65,1283.14) ; C145.1@759.26,1377.35 804.37,1377.35 v1(804.65,1377.63) ; C130.1@769.42,1569.48 772.3,1566.61 v1(804.65,1566.61) ; v1(836.14,1157.16) 836.4,1156.9 C142.1@836.42,1123.59 ; v1@867.85,1346.35 v1(867.64,1346.14) 894.49,1346.14 C129.1@899.42,1341.21 ; C147.1@993.4,1249.35 1006.4,1236.35 ; C141.1@1006.42,1562.35 1055.4,1562.35 C126.1@1061.4,1568.35 1088.85,1568.35 v1@1089.11,1568.61 ; 1041.32,1236.35 v1(1056.62,1251.65) ; C104.1@1047.17,593.13 v1(1078.67,593.13) ; v1(1056.62,1472.12) 1086.63,1472.12 C127.1@1091.4,1467.35 ; v1(1088.11,1157.16) 1088.4,1156.87 C143.1@1088.4,1123.59 ; v1(1088.11,1220.15) 1088.31,1220.35 C128.1@1133.4,1220.35 ; v1(1088.11,1314.64) 1131.79,1314.64 C144.1@1133.5,1316.35 ; v1(1362.42,1410.35) 1362.5,1410.27 C118.1@1399.92,1410.27 ; C95.1@1453.78,1285.35 1496.96,1285.35 v1(1499.17,1283.14) ; C100.1@1453.78,1377.35 1498.89,1377.35 v1(1499.17,1377.63) ; C122.1@1453.92,1564.78 1497.35,1564.78 v1(1499.17,1566.61) ; v1(1499.17,1251.65) 1500.47,1250.35 C96.1@1531.42,1250.35 ; C97.1@1533.42,1123.59 1533.42,1128.42 v1(1562.16,1157.16) ; v1(1562.16,1346.14) 1562.37,1346.35 C99.1@1592.92,1346.35 ; C94.1@1701.42,1566.35 1753.92,1566.35 C123.1@1755.92,1568.35 1783.37,1568.35 v1@1783.63,1568.61 ; C120.1@1720.42,1220.35 1720.42,1220.93 v1(1751.14,1251.65) ; v1(1751.14,1472.12) 1761.14,1462.12 C124.1@1781.15,1462.12 ; v1(1782.63,1157.16) 1782.92,1156.87 C119.1@1782.92,1123.59 ; v1(1782.63,1220.15) 1782.83,1220.35 C121.1@1827.92,1220.35 ; v1(1782.63,1314.64) 1791.92,1305.35 C98.1@1828.02,1305.35 ; C148.1@2006.93,1410.27 v1(2046.85,1410.27) v1@2046.93,1410.35 ; C154.1@2060.79,1189.35 2075.38,1189.35 v1(2106.18,1220.15) ; C153.1@2060.79,1285.35 2103.97,1285.35 v1(2106.18,1283.14) ; C149.1@2060.79,1377.35 2105.9,1377.35 v1(2106.18,1377.63) ; C137.1@2060.93,1564.78 2104.36,1564.78 v1(2106.18,1566.61) ; v1(2137.67,1157.16) 2137.93,1156.9 C135.1@2137.93,1123.59 ; v1(2169.17,1346.14) v1@2169.38,1346.35 ; C133.1@2294.93,1249.35 2308.38,1235.9 ; 2342.4,1235.9 v1(2358.15,1251.65) ; v1(2358.15,1472.12) C151.1@2388.16,1472.12 C151.1@2392.93,1467.35 ; C138.1@2362.93,1578.35 2380.38,1578.35 v1@2390.38,1568.35 ; v1(2389.64,1157.16) 2389.93,1156.87 C136.1@2389.93,1123.59 ; v1(2389.64,1220.15) 2389.84,1220.35 C152.1@2434.93,1220.35 ; v1(2389.64,1314.64) C150.1@2433.32,1314.64 C150.1@2435.03,1316.35 ; v1@2389.64,1568.35 v1@2390.38,1568.35 ; v1@2390.64,1568.61 v1@2390.38,1568.35 ; v1(2441.45,1562.61) 2443.42,1560.64 C132.1@2443.42,1511.35 v1(2480.42,1511.35)
  BOTTOM w12: C106.1@1046.42,498.35 1078.39,498.35 v1(1078.67,498.64) ; v1(1110.17,593.13) 1134.2,593.13 C102.1@1140.42,599.35 ; C103.1@1141.42,555.35 1141.42,598.35 C102.1@1140.42,599.35 ; C109.1@1200.42,558.35 1200.42,580.35 1187.64,593.13 v1(1173.16,593.13) 1166.94,599.35 C102.1@1140.42,599.35 ; v1(1236.15,593.13) 1235.42,592.4 1235.42,563.35 1240.42,558.35 C107.1@1266.42,558.35 ; v1(1330.64,593.13) 1331.42,592.34 C105.1@1331.42,555.35 ; v1(1362.14,593.13) 1375.42,579.84 C108.1@1375.42,555.49 ; v1(2169.17,1346.14) 2191.96,1323.35 C134.1@2200.42,1323.35
  other v1: 119.42,788.89 147.42,788.89 91.42,820.89 119.42,820.89 147.42,820.89 119.42,848.89 147.42,848.89 1783.63,1567.61
ZQPAD: R73.1 U1.AE17 | length 90
  TOP w6: U1.AE17@1125.92,797.85 1125.92,821.85 1135.42,831.35 1135.42,868.35 R73.1@1146.42,879.35
pads on no net: U1.A2 U1.A3 U1.A5 U1.A6 U1.A7 U1.A9 U1.A10 U1.A11 U1.A12 U1.A14 U1.A15 U1.A16 U1.A17 U1.A18 U1.A19 U1.A20 U1.A21 U1.A22 U1.A23 U1.A24 U1.AA1 U1.AA2 U1.AA3 U1.AA4 U1.AB1 U1.AB2 U1.AD14 U1.AE14 U1.B1 U1.B2 U1.B3 U1.B5 U1.B6 U1.B7 U1.B8 U1.B9 U1.B10 U1.B11 U1.B12 U1.B13 U1.B14 U1.B15 U1.B16 U1.B17 U1.B18 U1.B19 U1.B20 U1.B21 U1.B22 U1.B23 U1.B24 U1.B25 U1.C2 U1.C3 U1.C5 U1.C7 U1.C8 U1.C9 U1.C11 U1.C12 U1.C13 U1.C14 U1.C15 U1.C16 U1.C17 U1.C18 U1.C19 U1.C20 U1.C21 U1.C22 U1.C23 U1.C24 U1.C25 U1.D1 U1.D2 U1.D4 U1.D5 U1.D7 U1.D9 U1.D10 U1.D11 U1.D12 U1.D13 U1.D14 U1.D15 U1.D16 U1.D17 U1.D18 U1.D19 U1.D20 U1.D21 U1.D22 U1.D23 U1.D24 U1.D25 U1.E1 U1.E2 U1.E3 U1.E4 U1.E8 U1.E9 U1.E10 U1.E11 U1.E12 U1.E13 U1.E14 U1.E15 U1.E16 U1.E17 U1.E18 U1.E19 U1.E20 U1.E21 U1.E22 U1.E23 U1.E24 U1.E25 U1.F1 U1.F2 U1.F3 U1.F4 U1.F9 U1.F10 U1.F11 U1.F12 U1.F13 U1.F14 U1.F15 U1.F16 U1.F17 U1.F18 U1.F19 U1.F20 U1.F21 U1.F22 U1.F23 U1.F24 U1.F25 U1.G1 U1.G2 U1.G4 U1.G5 U1.G6 U1.G7 U1.G8 U1.G9 U1.G11 U1.G12 U1.G13 U1.G14 U1.G15 U1.G16 U1.G17 U1.G18 U1.G20 U1.G21 U1.G22 U1.G23 U1.G24 U1.G25 U1.H1 U1.H2 U1.H3 U1.H4 U1.H5 U1.H6 U1.H7 U1.H9 U1.H10 U1.H11 U1.H13 U1.H14 U1.H16 U1.H17 U1.H19 U1.H20 U1.H21 U1.H22 U1.H23 U1.H24 U1.H25 U1.J1 U1.J3 U1.J4 U1.J5 U1.J6 U1.J7 U1.J9 U1.J10 U1.J11 U1.J13 U1.J14 U1.J16 U1.J17 U1.J19 U1.J20 U1.J21 U1.J22 U1.J23 U1.J24 U1.J25 U1.K1 U1.K2 U1.K3 U1.K4 U1.K5 U1.K6 U1.K7 U1.K9 U1.K11 U1.K13 U1.K14 U1.K16 U1.K17 U1.K19 U1.K20 U1.K21 U1.K22 U1.K23 U1.K24 U1.K25 U1.L1 U1.L3 U1.L4 U1.L6 U1.L7 U1.L9 U1.L11 U1.L13 U1.L14 U1.L16 U1.L17 U1.L19 U1.L20 U1.L21 U1.L22 U1.L23 U1.L24 U1.L25 U1.M1 U1.M2 U1.M3 U1.M4 U1.M5 U1.M6 U1.M7 U1.M9 U1.M11 U1.M13 U1.M14 U1.M16 U1.M17 U1.M19 U1.M20 U1.M21 U1.M22 U1.M23 U1.M24 U1.M25 U1.N1 U1.N2 U1.N3 U1.N4 U1.N5 U1.N6 U1.N7 U1.N9 U1.N11 U1.N12 U1.N13 U1.N14 U1.N16 U1.N17 U1.N19 U1.N20 U1.N21 U1.N22 U1.N23 U1.N24 U1.N25 U1.P1 U1.P2 U1.P3 U1.P4 U1.P5 U1.P6 U1.P7 U1.P9 U1.P11 U1.P13 U1.P14 U1.P16 U1.P17 U1.P19 U1.P20 U1.P21 U1.P22 U1.P23 U1.P24 U1.P25 U1.R1 U1.R2 U1.R3 U1.R4 U1.R5 U1.R6 U1.R7 U1.R9 U1.R10 U1.R11 U1.R13 U1.R14 U1.R16 U1.R19 U1.R20 U1.R21 U1.R22 U1.R23 U1.R24 U1.R25 U1.T1 U1.T2 U1.T3 U1.T4 U1.T5 U1.T6 U1.T7 U1.T9 U1.T10 U1.T13 U1.T14 U1.T16 U1.T20 U1.T21 U1.T22 U1.T23 U1.T24 U1.T25 U1.U1 U1.U2 U1.U3 U1.U4 U1.U5 U1.U6 U1.U7 U1.U9 U1.U10 U1.U13 U1.U14 U1.U16 U1.U20 U1.U21 U1.U22 U1.U23 U1.U24 U1.U25 U1.V1 U1.V2 U1.V3 U1.V4 U1.V5 U1.V6 U1.V7 U1.V20 U1.V21 U1.V22 U1.V23 U1.V24 U1.V25 U1.W1 U1.W2 U1.W4 U1.W5 U1.W6 U1.W20 U1.W21 U1.W22 U1.W23 U1.W24 U1.Y1 U1.Y2 U1.Y3 U1.Y4 U2.J1 U2.J9 U2.L1 U2.L9 U3.J1 U3.J9 U3.L1 U3.L9 U4.J1 U4.J9 U4.L1 U4.L9 U5.J1 U5.J9 U5.L1 U5.L9 U15.7

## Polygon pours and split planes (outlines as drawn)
N31313358 on TOP "TOP-No Net" (hatched 90Degree grid 4 track 5, remove dead copper, pour order 1001): 220,418.35 220,520.35 55.42,520.35 55.42,462.35 153.42,462.35 153.42,418.35
VDD_1V5 on TOP "TOP-No Net" (hatched 90Degree grid 4 track 5, remove dead copper, pour order 1002): 195.42,860.35 195.42,618.35 47,618.35 47,860.35
GND on TOP "TOP-No Net" (hatched 90Degree grid 4 track 5, remove dead copper, pour order 1000): -124.58,2050.35 2708.89,2050.35 2708.89,1332.35 2708.89,-118.11 1096.42,-118.11 -124.58,-118.11 -124.58,2050.35
GND on TOP "TOP-No Net" (hatched 90Degree grid 4 track 5, remove dead copper, pour order 1003): -12.58,699.35 -45.41,699.35 -45.41,736.35 -45.41,863.35 -6.58,863.35 29.42,863.35 29.42,845.35 29.42,699.35 -12.58,699.35
N31313342 on TOP "TOP-No Net" (hatched 90Degree grid 4 track 5, remove dead copper, pour order 1000): 409.42,409.35 398.42,420.35 398.42,461.35 390.42,469.35 314.42,469.35 314.42,419.89 346.42,419.89 346.42,235.35 409.42,235.35
GND on BOTTOM "TOP-No Net" (hatched 90Degree grid 4 track 5, remove dead copper, pour order 1001): -124.58,2050.35 2708.89,2050.35 2708.89,1332.35 2708.89,-118.11 1096.42,-118.11 -124.58,-118.11 -124.58,2050.35
VDD_1V5 on BOTTOM "TOP-No Net" (hatched 90Degree grid 4 track 5, remove dead copper, pour order 1000): 1225.42,549.35 1108.42,549.35 1108.42,486.35 1041.42,486.35 1041.42,624.63 1395.42,624.63 1395.42,545.35 1258.42,545.35 1258.42,475.35 1225.42,475.35
GND on ART03 "TOP-No Net" (hatched 90Degree grid 4 track 5, remove dead copper, pour order 1002): -124.58,2050.35 2708.89,2050.35 2708.89,1332.35 2708.89,-118.11 1096.42,-118.11 -124.58,-118.11 -124.58,2050.35
GND on ART06 "TOP-No Net" (hatched 90Degree grid 4 track 5, remove dead copper, pour order 1003): -124.58,2050.35 2708.89,2050.35 2708.89,1332.35 2708.89,-118.11 1096.42,-118.11 -124.58,-118.11 -124.58,2050.35
GND on ART04 "TOP-No Net" (hatched 90Degree grid 4 track 5, remove dead copper, pour order 1004): -124.58,2050.35 2708.89,2050.35 2708.89,1332.35 2708.89,-118.11 1096.42,-118.11 -124.58,-118.11 -124.58,2050.35
GND on GND07 (split plane): 2688.79,-98.01 -98.01,-98.01 -98.01,2027.15 2688.79,2027.15
VDD_1V5 on GND02 (split plane): 2688.79,-98.01 -98.01,-98.01 -98.01,2027.15 2688.79,2027.15
GND on PWR05 (split plane): 2559.42,1923.35 2648.8,1923.35 2648.8,703.44 1796.42,703.44 1793.81,703.09 1791.38,702.08 1789.29,700.48 1707.77,618.97 1476.95,618.97 1474.34,618.62 1471.91,617.61 1469.82,616.01 1425.52,571.71 1191.7,571.71 1189.09,571.37 1186.65,570.36 1184.56,568.76 1093.04,477.23 705.8,477.23 488.55,694.48 486.46,696.08 484.03,697.09 481.42,697.44 -58.02,697.44 -58.02,1919.35 6.42,1919.35 6.42,1987.15 2559.42,1987.15
GND on PWR05 (split plane): 2648.8,24.35 2576.42,24.35 2576.42,-58.02 9.42,-58.02 9.42,12.35 -58.02,12.35 -58.02,677.26 477.24,677.26 694.49,460.01 696.58,458.41 697.8,457.91 699.01,457.4 701.62,457.06 1097.22,457.06 1099.83,457.4 1102.26,458.41 1104.35,460.01 1195.87,551.54 1429.7,551.54 1432.31,551.88 1434.74,552.89 1436.83,554.49 1481.13,598.79 1711.95,598.79 1714.56,599.14 1716.99,600.14 1719.08,601.75 1800.6,683.26 2648.8,683.26

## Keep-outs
Keep-Out Layer:
  the board outline again, w5.91

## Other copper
TOP:
  rectangle net VDD_1V5: 44,736 64.89,845
  rectangle net GND: 237.42,347.72 294.42,514.35
  rectangle net VDD_1V5: 99.42,628.35 160.89,674.35
  rectangle net VDD_1V5: 64.89,657.35 120.42,724.89
  rectangle net VDD_1V5: 64.89,711.35 104.89,738.35
  rectangle net N31313358: 105.42,466.35 160.89,519.35
  rectangle net N31313342: 346.42,245.35 405.42,301.35
  pour cut-out: 66.42,459.35 146.42,459.35 146.42,379.88 227.42,379.88 227.42,332.22 66.42,332.22
  pour cut-out: 2287.93,1756.89 2287.93,1479.35 2330.93,1479.35 2330.93,1332.35 2177.93,1332.35 2177.93,1756.89
  pour cut-out: 1680.92,1756.89 1680.92,1479.35 1723.92,1479.35 1723.92,1332.35 1570.92,1332.35 1570.92,1756.89
  pour cut-out: 986.4,1756.89 986.4,1479.35 1029.4,1479.35 1029.4,1332.35 876.4,1332.35 876.4,1756.89
  pour cut-out: 428.42,1756.89 428.42,1479.35 471.42,1479.35 471.42,1332.35 318.42,1332.35 318.42,1756.89
  text "TOP" at -346.58,2225.35 h80
ART03:
  pour cut-out: 2074.42,1370.35 2173.42,1370.35 2173.42,1330.39 2074.42,1330.39
  pour cut-out: 2313.85,1368.89 2418.42,1368.89 2418.42,1131.35 2286.92,1131.35 2286.92,1283.14 2318.42,1283.14 2318.42,1376.35
  pour cut-out: 1931.42,1208.35 2057.42,1208.35 2057.42,1075.2 1619.42,1075.2 1619.42,1317.35 1766.88,1317.35 1766.88,1165.35 1931.42,1165.35
  pour cut-out: 1101.42,1369.35 1218.42,1252.35 1664.42,1252.35 1664.42,981.35 1914.42,981.35 1914.42,733.35 1694.42,733.35 1694.42,656.12 1300.42,656.12 1300.42,708.35 1103.42,708.35 1103.42,664.35 968.44,664.35 968.44,721.35 930.42,721.35 930.42,703.36 727.41,703.36 370.42,1060.35 267.42,1060.35 225.42,1102.35 225.42,1158.35 299.42,1232.35 450.42,1232.35 473.42,1209.35 487.42,1209.35 487.42,1124.35 585.42,1124.35 585.42,1369.35
  pour cut-out: 2090.42,1829.35 2206.68,1713.09 2206.68,1422.04 2185.71,1401.06 2177.42,1409.35 2123.42,1409.35 2065.42,1467.35 1777.85,1467.35 1677.85,1367.35 1666.95,1367.35 1615.42,1418.88 1615.42,1719.59 1725.18,1829.35
  pour cut-out: 770.42,1805.35 770.42,1765.35 944.36,1765.35 944.36,1414.35 888.42,1414.35 839.42,1463.35 531.42,1463.35 444.96,1376.89 391.42,1376.89 391.42,1390.38 357.11,1424.69 357.11,1743.04 419.42,1805.35
  text "ART03" at 381.42,2225.35 h80
ART04:
  pour cut-out: 1438.42,1605.85 1438.42,1270.16 1213.18,1270.16 1213.18,819.35 1299.15,819.35 1299.15,640.35 1259.42,640.35 1259.42,541.35 1188.91,541.35 1188.91,656.35 913.42,656.35 913.42,1091.35 1171.42,1091.35 1171.42,1605.85
  pour cut-out: 2253.42,1787.35 2253.42,1767.35 2268.42,1767.35 2268.42,1415.35 2097.42,1415.35 2097.42,1449.85 1723.42,1449.85 1723.42,1787.35
  pour cut-out: 513.42,1769.35 870.42,1769.35 870.42,1491.35 455.42,1491.35 455.42,1748.35 513.42,1748.35
  text "ART04" at 838.42,2225.35 h80
ART06:
  pour cut-out: 1345.42,1325.35 1515.42,1325.35 1515.42,1360.35 1761.42,1360.35 1761.42,1045.37 2169.17,1045.37 2169.17,1246.35 2342.4,1246.35 2342.4,987.33 2113.42,758.35 1745.42,758.35 1636.42,649.35 1327.42,649.35 1281.42,695.35 1283.42,697.35 1283.42,1272.93 1340.4,1329.9
  pour cut-out: 757.55,1202.06 1119.42,1202.06 1119.42,882.35 1069.42,882.35 1069.42,656.35 923.42,656.35 923.42,550.35 785.47,550.35 630.42,705.4 630.42,1181.35 649.96,1200.89 750.42,1200.89
  pour cut-out: 329.42,1296.35 595.42,1296.35 595.42,995.35 262.42,995.35 262.42,1314.64 321.28,1314.64 321.28,1293.49
  pour cut-out: 752.82,1827.75 1882.42,1827.75 1882.42,1512.35 760.42,1512.35 760.42,1827.35
  text "ART06" at 1754.42,2225.35 h80
BOTTOM:
  rectangle net VDD_1V5: 1225.42,482.35 1246.42,518.35
  rectangle net VDD_1V5: 1104.42,576.52 1168.89,604.89
  pour cut-out: 1385.42,965.35 1385.42,763.35 1371.42,763.35 1371.42,624.62 1215.34,624.62 1215.34,740.35 1220.4,740.35 1220.4,851.35 1082.42,851.35 1082.42,965.35
  text "BOOTOM" at 3087.42,2225.35 h80
GND02 (plane layer: these items are gaps in the copper):
  text "GND02" at -72.58,2225.35 h80
PWR05 (plane layer: these items are gaps in the copper):
  rectangle: -103.58,1919.35 6.42,2009.35
  rectangle: -118.11,-118.11 9.42,12.35
  rectangle: 2576.42,-110.65 2681.42,24.35
  rectangle: 2559.42,1923.35 2689.42,2047.24
  lines w20: -92.58,687.35 481.42,687.35 701.62,467.15 1097.22,467.15 1191.7,561.63 1429.7,561.63 1476.95,608.88 1711.95,608.88 1796.42,693.35 2724.42,693.35
  text "PWR05" at 1289.42,2225.35 h80
GND07 (plane layer: these items are gaps in the copper):
  text "GND07" at 2186.42,2225.35 h80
